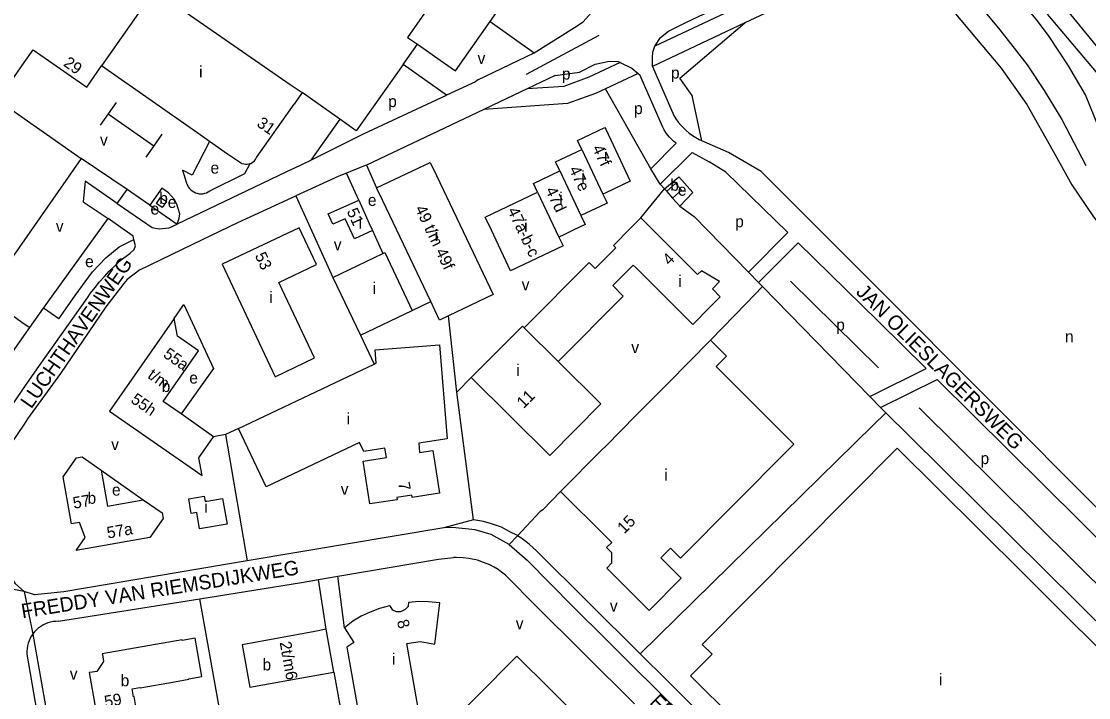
# Model space of a CAD drawing. Extents: x 154765 to 156627, y 383996 to 386132.
# Drawn here: x 155399 to 155766.1, y 385414.8 to 385647.4 of the extents above; entities that cross this region are included whole.
import ezdxf

# ---------------------------------------------------------------- set-up
doc = ezdxf.new("R2010")
doc.units = 0
for name, color, linetype in [('BLT_Basislijn', 7, 'Continuous'), ('BLT_Bebouwing', 7, 'Continuous'), ('BLT_Centroide', 7, 'Continuous'), ('BLT_Huisnummer', 7, 'Continuous'), ('BLT_Huisnummer_reeks', 7, 'Continuous'), ('BLT_Onderverdeling_panden', 7, 'Continuous'), ('BLT_Straatnaam', 7, 'Continuous'), ('BLT_Vlakafsluiter', 7, 'Continuous')]:
    doc.layers.add(name, color=color, linetype=linetype)

msp = doc.modelspace()

# ---------------------------------------------------------------- linework, layer by layer
at = {"layer": 'BLT_Basislijn'}
for p, q in [((155723.16, 385695.09), (155782.92, 385621.52)), ((155560.27, 385647.4), (155575.39, 385636.61)), ((155647.86, 385646.85), (155616.07, 385631.86)), ((155777.49, 385619.55), (155751.97, 385649.86)), ((155530.34, 385632.56), (155535.27, 385639.52)), ((155572.82, 385629.26), (155597.76, 385642.66)), ((155556.04, 385627.27), (155575.39, 385636.61)), ((155616.19, 385636.83), (155616.86, 385638.87)), ((155616.07, 385631.86), (155623.4, 385614.99)), ((155582.65, 385628.77), (155572.99, 385624.19)), ((155611.12, 385629.52), (155599.93, 385624.25)), ((155611.12, 385629.52), (155611.75, 385628.98)), ((155572.99, 385624.19), (155563.61, 385619.74)), ((155615.48, 385596.71), (155599.93, 385624.25)), ((155558.13, 385617.14), (155517.79, 385598.01)), ((155563.61, 385619.74), (155558.13, 385617.14)), ((155633.12, 385606.31), (155632.31, 385606.68)), ((155435.37, 385589.63), (155419.58, 385600.25)), ((155629.7, 385602.29), (155635.61, 385599.15)), ((155492.62, 385596.82), (155452.63, 385577.61)), ((155515.06, 385585.86), (155510.85, 385595.23)), ((155431.98, 385584.75), (155435.37, 385589.63)), ((155441.07, 385585.66), (155435.37, 385589.63)), ((155576.6, 385588.63), (155583.89, 385573.23)), ((155620.29, 385589.76), (155621, 385588.96)), ((155623.04, 385586.63), (155625.52, 385583.84)), ((155625.52, 385583.84), (155630.42, 385580.25)), ((155406.62, 385548.82), (155428.82, 385579.63)), ((155630.42, 385580.25), (155649.08, 385561.15)), ((155519.75, 385575.43), (155523.3, 385567.53)), ((155649.08, 385561.15), (155662.66, 385574.74)), ((155439.8, 385562), (155458.04, 385570.8)), ((155652.57, 385557.58), (155666.24, 385571.25)), ((155649.08, 385561.15), (155652.57, 385557.58)), ((155648.31, 385550.38), (155653.93, 385556.19)), ((155652.57, 385557.58), (155653.93, 385556.19)), ((155653.93, 385556.19), (155690.88, 385518.37)), ((155693.87, 385528.3), (155663.54, 385558.1)), ((155533.49, 385548.01), (155539.85, 385551.04)), ((155401.91, 385542.08), (155406.62, 385548.82)), ((155411.92, 385545.13), (155406.62, 385548.82)), ((155636.09, 385537.77), (155648.31, 385550.38)), ((155548.76, 385519.85), (155545.99, 385546.18)), ((155571.95, 385542.04), (155583.69, 385530.46)), ((155515.62, 385539.49), (155520.38, 385529.51)), ((155690.88, 385518.37), (155710.26, 385527.98)), ((155553.79, 385524.89), (155548.76, 385519.85)), ((155694.55, 385514.61), (155714.02, 385524.27)), ((155554.53, 385476.04), (155548.76, 385519.85)), ((155690.88, 385518.37), (155694.55, 385514.61)), ((155694.55, 385514.61), (155696.37, 385512.8)), ((155813.32, 385409.81), (155707.88, 385514.52)), ((155696.37, 385512.8), (155692.05, 385508.54)), ((155696.37, 385512.8), (155704.4, 385504.85)), ((155473.71, 385507.4), (155469.26, 385505.29)), ((155692.05, 385508.54), (155611.87, 385429.93)), ((155469.26, 385505.29), (155465.15, 385504.52)), ((155469.26, 385505.29), (155476.69, 385461.86)), ((155704.4, 385504.85), (155814.96, 385395.3)), ((155426.46, 385493.05), (155440.95, 385482.9)), ((155554.53, 385476.04), (155544.31, 385473.21)), ((155510.11, 385438.88), (155507.87, 385456.56)), ((155503.88, 385438.34), (155501.23, 385455.42)), ((155411.75, 385441.09), (155460.46, 385448.85)), ((155468.15, 385405.36), (155460.46, 385448.85)), ((155400.95, 385429.81), (155412.57, 385362.07)), ((155608.76, 385426.23), (155608.96, 385426.03)), ((155506.52, 385423.64), (155511.8, 385393.87))]:
    msp.add_line(p, q, dxfattribs=at)
for points in [[(156007.6, 385344.92), (155996.28, 385354.88), (155980.49, 385371.12), (155972.14, 385379.04), (155965.68, 385384.27), (155957.28, 385390.42), (155944.89, 385398.75), (155936.89, 385404.83), (155929.87, 385410.58), (155925.23, 385414.81), (155918.35, 385421.09), (155902.63, 385438.73), (155854.03, 385494.81), (155800.47, 385556.64), (155793.89, 385564.54), (155785.69, 385576.1), (155777.93, 385590.57), (155771.46, 385606.33), (155765, 385622.09), (155759.19, 385632.12), (155752.51, 385642.23), (155748.51, 385647.55), (155714.99, 385688.08)], [(155705.97, 385680.31), (155735.54, 385644.51), (155745.02, 385632.44), (155750.86, 385623.61), (155756.86, 385613.62), (155765.1, 385597.81)], [(155616.86, 385638.87), (155618.82, 385641.82), (155621.63, 385644.09), (155627.62, 385646.96), (155659.11, 385662), (155670.08, 385667.83), (155674.86, 385671.1), (155685.15, 385678.21)], [(155688.15, 385673.62), (155687.58, 385673.11), (155682.11, 385669.63), (155616.86, 385638.87)], [(155699.96, 385674.45), (155691.21, 385668.31), (155685.01, 385664.36), (155647.86, 385646.85)], [(155699.96, 385674.45), (155716.73, 385654.28), (155725.17, 385644.24), (155735.98, 385631.29), (155744.84, 385618.79), (155753.89, 385602.72), (155760.37, 385591.15), (155767.75, 385580.16), (155776.01, 385569.79), (155821.88, 385516.23)], [(155575.39, 385636.61), (155589.29, 385645.25), (155592.25, 385647.23), (155594.99, 385650.37), (155596.39, 385654.14), (155596.54, 385657.23), (155595.72, 385660.82)], [(155633.12, 385606.31), (155629.78, 385621.92), (155625.54, 385627.85), (155647.86, 385646.85)], [(155616.06, 385631.81), (155616.06, 385634.83), (155616.19, 385636.83)], [(155530.34, 385632.56), (155514.2, 385609.78)], [(155545.26, 385622.03), (155530.34, 385632.56)], [(155605.03, 385633.29), (155594.18, 385628.17), (155585.57, 385625.06), (155572.99, 385624.19)], [(155582.65, 385628.77), (155591.04, 385629.97), (155596.44, 385632.74), (155601.35, 385633.77), (155604.34, 385633.63), (155605.03, 385633.29)], [(155605.03, 385633.29), (155609, 385631.33), (155611.12, 385629.52)], [(155615.48, 385596.71), (155624.28, 385605.49), (155623.49, 385606.09), (155622.7, 385606.78), (155621.96, 385607.54), (155621.29, 385608.35), (155620.68, 385609.21), (155620.13, 385610.11), (155619.65, 385611.05), (155619.25, 385612.02), (155611.75, 385628.98)], [(155556.04, 385627.27), (155555.18, 385626.57), (155545.26, 385622.03)], [(155508.57, 385613.75), (155495.57, 385622.9)], [(155498.6, 385599.66), (155516.74, 385608.77), (155545.26, 385622.03)], [(155599.93, 385624.25), (155596.48, 385622.62), (155586.82, 385619.14), (155558.13, 385617.14)], [(155431.63, 385619.54), (155428.88, 385615.63)], [(155428.88, 385615.63), (155426.12, 385611.71)], [(155428.88, 385615.63), (155444.63, 385604.65)], [(155508.57, 385613.75), (155498.6, 385599.66)], [(155514.2, 385609.78), (155508.57, 385613.75)], [(155623.4, 385614.99), (155624.14, 385613.86), (155624.95, 385612.78), (155625.81, 385611.74), (155626.74, 385610.76), (155627.72, 385609.83), (155628.76, 385608.97), (155629.84, 385608.17), (155630.97, 385607.43), (155632.15, 385606.76), (155632.31, 385606.68)], [(155447.38, 385608.56), (155444.63, 385604.65)], [(155463.74, 385606.13), (155457.81, 385594.48), (155454.4, 385596.27)], [(155653.48, 385595.79), (155642.26, 385602.27), (155633.12, 385606.31)], [(155444.63, 385604.65), (155441.88, 385600.73)], [(155492.62, 385596.82), (155498.6, 385599.66)], [(155629.7, 385602.29), (155618.77, 385591.45)], [(155662.66, 385574.74), (155641.38, 385595.56), (155635.61, 385599.15)], [(155454.4, 385596.27), (155455.83, 385591.78), (155455.88, 385591.64), (155456.12, 385591.05), (155456.44, 385590.48), (155456.83, 385589.97), (155457.27, 385589.5), (155457.77, 385589.09), (155458.32, 385588.75), (155458.91, 385588.47), (155459.52, 385588.27), (155460.16, 385588.15), (155460.8, 385588.11), (155461.45, 385588.15), (155462.08, 385588.27), (155462.7, 385588.46), (155463.29, 385588.73), (155463.84, 385589.07), (155475.84, 385595.14), (155477.77, 385598.5)], [(155510.85, 385595.23), (155508.22, 385594.18), (155493.42, 385587.4)], [(155517.79, 385598.01), (155517.28, 385597.8), (155510.85, 385595.23)], [(155517.79, 385598.01), (155521.2, 385590.15)], [(155618.77, 385591.45), (155615.48, 385596.71)], [(155653.48, 385595.79), (155693, 385556.19)], [(155431.98, 385584.75), (155421.02, 385592.43), (155420.27, 385585.32), (155428.82, 385579.63)], [(155620.29, 385589.76), (155618.77, 385591.45)], [(155620.29, 385589.76), (155625.15, 385593.97), (155629.99, 385588.56), (155625.52, 385583.84)], [(155452.63, 385577.61), (155453.35, 385579.71), (155453.56, 385581.25), (155452.98, 385583.05), (155452.45, 385584.58), (155451.66, 385586.17), (155449.59, 385588.44), (155447.37, 385590.08), (155443.19, 385584.18)], [(155612.12, 385579.79), (155620.29, 385589.76)], [(155431.98, 385584.75), (155444.05, 385576.53), (155446.46, 385576.1), (155449.83, 385576.4), (155452.63, 385577.61)], [(155443.19, 385584.18), (155441.07, 385585.66)], [(155443.19, 385584.18), (155452.63, 385577.61)], [(155458.04, 385570.8), (155473.5, 385578.26), (155493.42, 385587.4)], [(155493.42, 385587.4), (155506.19, 385559.36)], [(155437.72, 385572.43), (155437.43, 385573.59), (155431.25, 385577.93), (155428.82, 385579.63)], [(155400, 385521.46), (155405.2, 385529.04), (155421.81, 385552.34), (155422.85, 385553.9), (155424.36, 385555.87), (155425.93, 385557.79), (155427.57, 385559.65), (155429.26, 385561.47), (155431.01, 385563.22), (155432.82, 385564.92), (155433.44, 385565.48), (155436.34, 385567.6), (155437.78, 385568.94), (155438.25, 385570.25), (155437.72, 385572.43)], [(155414.1, 385548.24), (155417.49, 385553.11), (155423.44, 385561.22), (155428.11, 385566.07), (155432.68, 385569.88), (155437.72, 385572.43)], [(155710.26, 385527.98), (155693.74, 385544.35), (155666.24, 385571.25)], [(155439.8, 385562), (155435.38, 385558.64), (155434.27, 385557.21)], [(155583.69, 385530.46), (155606.05, 385552.93), (155602.43, 385556.53), (155609.47, 385563.61), (155610.46, 385562.6), (155629.95, 385543.2), (155635.86, 385549.12)], [(155434.27, 385557.21), (155428.12, 385549.28), (155412.45, 385526.36), (155401.18, 385510.7), (155400, 385508.92)], [(155693, 385556.19), (155770.64, 385478.39)], [(155411.92, 385545.13), (155414.1, 385548.24)], [(155451.62, 385545.26), (155454.92, 385549.99), (155465.11, 385528.06), (155453.94, 385512.39)], [(155571.95, 385542.04), (155571.38, 385542.61), (155553.79, 385524.89)], [(155553.79, 385524.89), (155580.74, 385498.13), (155598.35, 385515.86), (155583.69, 385530.46)], [(155814.96, 385395.3), (155815.81, 385396.15), (155818.5, 385396.69), (155824.21, 385402.45), (155826.6, 385406.47), (155826.75, 385410.3), (155826.12, 385412.36), (155824.68, 385414.68), (155714.02, 385524.27)], [(155383.82, 385490.77), (155384.04, 385492.42), (155384.35, 385494.06), (155384.74, 385495.68), (155385.2, 385497.29), (155385.74, 385498.86), (155386.35, 385500.42), (155387.04, 385501.93), (155387.8, 385503.42), (155389.15, 385505.62), (155400, 385521.46)], [(155400, 385508.92), (155395.45, 385502.1), (155392.4, 385497.33), (155390.49, 385492.93), (155390.21, 385490.83)], [(155400, 385451.33), (155397.05, 385453.93), (155395.65, 385456.27), (155392.92, 385471.02), (155390.15, 385489.01), (155390.21, 385490.83)], [(155584.47, 385485.73), (155578.33, 385479.43), (155577.46, 385478.87), (155569.66, 385470.53)], [(155569.62, 385470.56), (155567, 385471.89), (155564.19, 385473.44), (155560.73, 385474.64), (155557.92, 385475.36), (155554.53, 385476.04)], [(155544.31, 385473.21), (155476.69, 385461.86)], [(155566.78, 385467.46), (155560.62, 385470.91), (155555.14, 385472.54), (155547.33, 385473.33), (155544.31, 385473.21)], [(155569.66, 385470.53), (155566.78, 385467.46)], [(155569.66, 385470.53), (155569.62, 385470.56)], [(155611.87, 385429.93), (155576.24, 385465.34), (155575.07, 385466.41), (155573.68, 385467.61), (155572.19, 385468.81), (155570.82, 385469.75), (155569.66, 385470.53)], [(155566.78, 385467.46), (155572.95, 385462.09), (155588.99, 385445.94), (155600, 385434.96), (155608.76, 385426.23)], [(155507.87, 385456.56), (155542.49, 385462.51), (155547.68, 385462.98)], [(155609.89, 385412.76), (155575.43, 385447), (155566.59, 385455.92), (155565.51, 385457), (155564.19, 385458.03), (155562.99, 385458.85), (155561.59, 385459.71), (155560.11, 385460.47), (155558.02, 385461.34), (155555.91, 385462.06), (155552.98, 385462.73), (155550.98, 385462.93), (155548.56, 385463.03), (155547.68, 385462.98)], [(155476.69, 385461.86), (155413.68, 385451.28), (155403.58, 385450.23), (155400, 385451.33)], [(155501.23, 385455.42), (155507.87, 385456.56)], [(155460.46, 385448.85), (155495.41, 385454.42), (155501.23, 385455.42)], [(155411.75, 385441.09), (155410.83, 385441.07), (155409.92, 385440.97), (155409.02, 385440.79), (155408.13, 385440.54), (155407.27, 385440.21), (155406.45, 385439.8), (155405.66, 385439.33), (155404.92, 385438.79), (155404.22, 385438.18), (155403.58, 385437.52), (155403, 385436.81), (155402.92, 385436.68)], [(155402.92, 385436.68), (155402.49, 385436.05), (155402.04, 385435.24), (155401.67, 385434.4), (155401.36, 385433.53), (155401.14, 385432.64), (155400.99, 385431.73), (155400.93, 385430.81), (155400.95, 385429.81)], [(155402.92, 385436.68), (155416.02, 385362.7)], [(155734.6, 385315.13), (155731.84, 385314.84), (155730.71, 385314.86), (155729.51, 385315.05), (155728.37, 385315.4), (155727.12, 385315.99), (155726.14, 385316.67), (155724.68, 385317.83), (155696.18, 385346.15), (155649.48, 385392.56), (155621.13, 385420.73), (155611.87, 385429.93)], [(155608.96, 385426.03), (155653.28, 385382.33), (155713.58, 385322.08), (155720.5, 385315.89), (155722.31, 385314.59), (155724.99, 385313.76), (155727.79, 385313.46), (155733.17, 385314.1), (155734.6, 385315.13)]]:
    msp.add_lwpolyline(points, dxfattribs=at)
at = {"layer": 'BLT_Bebouwing'}
for p, q in [((155531.87, 385641.88), (155535.27, 385639.52)), ((155460.49, 385608.4), (155426.64, 385632.06)), ((155391.01, 385620.24), (155419.58, 385600.25)), ((155479.95, 385600.6), (155492.81, 385618.95)), ((155463.74, 385606.13), (155460.49, 385608.4)), ((155477.77, 385598.5), (155477.91, 385598.56)), ((155624.06, 385591.68), (155621, 385588.96)), ((155558.54, 385580.07), (155576.6, 385588.63)), ((155621, 385588.96), (155620.99, 385588.95)), ((155620.99, 385588.95), (155623.04, 385586.63)), ((155621.41, 385522.9), (155636.09, 385537.77)), ((155714.34, 385486.7), (155700.3, 385500.65)), ((155728.43, 385472.7), (155714.34, 385486.7)), ((155743.74, 385457.49), (155728.43, 385472.7)), ((155759.92, 385441.42), (155743.74, 385457.49)), ((155780.3, 385421.17), (155759.92, 385441.42)), ((155506.52, 385423.64), (155503.88, 385438.34)), ((155597.88, 385400.95), (155569.49, 385429.14))]:
    msp.add_line(p, q, dxfattribs=at)
for points in [[(155552.89, 385672.11), (155531.87, 385641.88)], [(155560.27, 385647.4), (155574.45, 385667.67)], [(155449.72, 385654.59), (155491.46, 385625.74), (155495.57, 385622.9)], [(155535.27, 385639.52), (155544.27, 385633.26), (155548.38, 385630.4), (155560.27, 385647.4)], [(155400, 385633.24), (155401.14, 385634.88), (155403.04, 385637.61)], [(155403.04, 385637.61), (155421.49, 385624.72), (155426.64, 385632.06)], [(155393.38, 385623.63), (155400, 385633.24)], [(155495.57, 385622.9), (155492.81, 385618.95)], [(155591.77, 385603.34), (155590.31, 385606.42), (155599.72, 385610.88), (155600, 385610.28), (155608.46, 385592.42)], [(155477.77, 385598.5), (155477.23, 385598.33), (155476.67, 385598.23), (155476.11, 385598.22), (155475.55, 385598.28), (155475, 385598.43), (155474.52, 385598.64), (155474.04, 385598.93), (155469.94, 385601.79), (155463.74, 385606.13)], [(155584.18, 385595.99), (155582.73, 385599.06), (155591.77, 385603.34)], [(155419.58, 385600.25), (155386.53, 385553), (155400, 385543.41)], [(155477.91, 385598.56), (155478.28, 385598.74), (155478.75, 385599.06), (155479.17, 385599.44), (155479.53, 385599.87), (155479.83, 385600.35), (155479.95, 385600.6)], [(155521.2, 385590.15), (155539.61, 385598.92), (155541.76, 385594.4), (155561.25, 385553.45), (155545.99, 385546.18)], [(155576.6, 385588.63), (155575.14, 385591.7), (155584.18, 385595.99)], [(155608.46, 385592.42), (155600, 385588.41), (155599.03, 385588.03)], [(155623.04, 385586.63), (155626.12, 385589.36), (155624.06, 385591.68)], [(155539.85, 385551.04), (155523.35, 385585.64), (155521.2, 385590.15)], [(155599.03, 385588.03), (155600, 385585.97), (155600.52, 385584.88), (155600, 385584.64), (155591.48, 385580.6)], [(155506.18, 385577.62), (155504.59, 385581.16), (155515.06, 385585.86)], [(155515.06, 385585.86), (155518.67, 385577.84)], [(155591.48, 385580.6), (155592.94, 385577.52), (155588.78, 385575.55), (155585.57, 385574.02), (155583.89, 385573.23)], [(155519.75, 385575.43), (155513.55, 385572.64), (155510.44, 385579.54), (155506.18, 385577.62)], [(155518.67, 385577.84), (155519.75, 385575.43)], [(155583.89, 385573.23), (155585.35, 385570.16), (155567.29, 385561.6), (155560.68, 385575.55), (155558.54, 385580.07)], [(155571.95, 385542.04), (155594.31, 385564.53), (155596.4, 385562.45), (155603.47, 385569.55), (155602.69, 385570.33), (155608.59, 385576.25), (155612.12, 385579.79)], [(155635.86, 385549.12), (155639.4, 385552.69), (155636.69, 385555.39), (155639.2, 385557.92), (155632.92, 385561.66), (155631.63, 385560.36), (155612.12, 385579.79)], [(155506.19, 385559.36), (155523.3, 385567.53)], [(155523.3, 385567.53), (155524.06, 385567.89), (155533.49, 385548.01)], [(155506.19, 385559.36), (155515.62, 385539.49)], [(155542.88, 385544.7), (155539.85, 385551.04)], [(155515.62, 385539.49), (155533.49, 385548.01)], [(155451.62, 385545.26), (155429.37, 385513.41), (155461.19, 385491.19), (155460.02, 385497.33), (155465.15, 385504.52)], [(155453.94, 385512.39), (155447.77, 385516.72), (155459.94, 385534.1), (155452.7, 385539.12), (155451.62, 385545.26)], [(155545.99, 385546.18), (155542.88, 385544.7)], [(155400, 385543.41), (155401.91, 385542.08)], [(155400, 385539.35), (155401.91, 385542.08)], [(155364.66, 385488.9), (155400, 385539.35)], [(155636.09, 385537.77), (155641.59, 385532.31), (155637.97, 385528.67)], [(155520.38, 385529.51), (155521.08, 385529.84), (155520.72, 385534.43)], [(155520.72, 385534.43), (155542.89, 385536.15), (155545.45, 385503.84)], [(155473.71, 385507.4), (155520.38, 385529.51)], [(155637.97, 385528.67), (155664.75, 385502.05), (155662.72, 385500), (155625.71, 385462.77), (155622.25, 385466.21), (155618.96, 385462.91)], [(155610.51, 385511.94), (155621.41, 385522.9)], [(155465.15, 385504.52), (155453.94, 385512.39)], [(155584.47, 385485.73), (155598.65, 385500), (155600, 385501.36), (155610.51, 385511.94)], [(155516.84, 385499.47), (155515.38, 385502.57), (155483.2, 385487.33), (155473.71, 385507.4)], [(155545.45, 385503.84), (155535.77, 385502.37), (155535.94, 385499.16), (155540.59, 385499.88), (155542.87, 385485.11), (155533.47, 385483.67), (155533.35, 385484.46), (155528.15, 385483.65), (155528.26, 385482.87), (155518.89, 385481.43), (155516.61, 385496.21), (155524.58, 385497.44), (155524.09, 385500.58), (155516.84, 385499.47)], [(155700.3, 385500.65), (155633.2, 385433.14), (155636.59, 385429.78), (155629.15, 385422.38)], [(155417.88, 385465.4), (155421.01, 385469.89), (155419.07, 385475.07), (155416.29, 385474.58), (155413.43, 385490.74), (155418.01, 385497.26), (155419.94, 385497.62), (155426.46, 385493.05)], [(155426.46, 385493.05), (155428.64, 385480.73), (155440.95, 385482.9)], [(155602.09, 385468.22), (155600, 385470.3), (155584.47, 385485.73)], [(155440.95, 385482.9), (155447.46, 385478.34), (155447.84, 385476.44), (155443.24, 385469.88), (155417.88, 385465.4)], [(155456.6, 385483.19), (155461.87, 385484.11), (155462.19, 385482.26), (155468.24, 385483.31), (155469.77, 385474.54), (155460.33, 385472.9), (155459.36, 385478.48), (155457.48, 385478.15), (155456.6, 385483.19)], [(155618.96, 385462.91), (155626.02, 385455.89), (155615.01, 385444.81), (155600.35, 385459.38), (155602.15, 385461.2), (155602.14, 385464.63), (155600.32, 385466.45), (155602.09, 385468.22)], [(155536.01, 385408.59), (155531.6, 385433.44), (155536.17, 385434.12), (155541.26, 385433.17), (155542.97, 385447.47), (155539.09, 385447.76), (155535.73, 385447.91), (155532.18, 385447.51), (155532.08, 385446.13), (155530.99, 385445.13), (155529.44, 385444.32), (155528.08, 385444.39), (155526.84, 385444.92), (155525.96, 385446.13), (155525.7, 385446.41), (155522.21, 385445.52), (155519.04, 385444.2), (155515.87, 385442.87), (155513, 385441.15), (155510.11, 385438.88)], [(155503.88, 385438.34), (155500, 385437.62), (155474.93, 385433.01), (155477.57, 385418.43), (155500, 385422.46), (155506.52, 385423.64)], [(155510.11, 385438.88), (155513.43, 385433.85), (155510.96, 385432.23)], [(155422.54, 385423.48), (155422.32, 385423.45), (155425.29, 385406.62), (155425.49, 385406.64), (155426.29, 385402.17), (155431.21, 385403.03), (155439.48, 385404.47), (155438.67, 385408.98), (155438.86, 385409.02), (155437.78, 385415.19), (155437.56, 385415.16), (155437.1, 385417.87), (155439.79, 385418.33), (155439.86, 385418.16), (155451.73, 385420.27), (155456.65, 385421.14), (155456.61, 385421.36), (155461.12, 385422.1), (155458.81, 385435.33), (155454.33, 385434.53), (155454.31, 385434.73), (155426.84, 385429.85), (155426.87, 385429.64)], [(155510.96, 385432.23), (155515.76, 385405.01), (155536.01, 385408.59)], [(155426.87, 385429.64), (155427.3, 385427.27), (155424.94, 385423.85), (155422.54, 385423.48)], [(155569.49, 385429.14), (155541.46, 385400.93)], [(155629.15, 385422.38), (155690.08, 385361.91), (155697.7, 385369.56), (155693.91, 385373.34)]]:
    msp.add_lwpolyline(points, dxfattribs=at)
for points in [[(155445.46, 385584.75), (155446.89, 385586.81), (155448.9, 385585.42), (155447.46, 385583.36)], [(155494.52, 385576.44), (155468.11, 385563.92), (155486.33, 385525.2), (155499.9, 385531.64), (155487.61, 385557.64), (155500.59, 385563.83)]]:
    msp.add_lwpolyline(points, close=True, dxfattribs=at)
at = {"layer": 'BLT_Onderverdeling_panden'}
for p, q in [((155444.78, 385658.01), (155426.64, 385632.06)), ((155591.77, 385603.34), (155599.03, 385588.03)), ((155584.18, 385595.99), (155591.48, 385580.6))]:
    msp.add_line(p, q, dxfattribs=at)
at = {"layer": 'BLT_Vlakafsluiter'}
for q in [(155389.47, 385453.36), (155402.92, 385436.68)]:
    msp.add_line((155400, 385451.33), q, dxfattribs=at)

# ---------------------------------------------------------------- texts
at = {"layer": 'BLT_Centroide'}
for s, p in [('v', (155555.93, 385632.76)), ('i', (155460.16, 385628.12)), ('p', (155584.94, 385627.38)), ('p', (155622.44, 385627.74)), ('p', (155525.17, 385617.92)), ('p', (155609.76, 385615.51)), ('v', (155426.06, 385604.66)), ('i', (155599.39, 385599.44)), ('e', (155464.08, 385595.05)), ('i', (155591.62, 385591.97)), ('b', (155622.22, 385589.16)), ('b', (155446.44, 385584.59)), ('i', (155584.05, 385584.62)), ('e', (155624.84, 385587.45)), ('e', (155443.42, 385580.97)), ('e', (155449.37, 385583.26)), ('e', (155518.21, 385583.94)), ('i', (155515.01, 385576.14)), ('v', (155410.86, 385575.04)), ('i', (155571.94, 385575.12)), ('p', (155644.54, 385576.61)), ('i', (155541.22, 385571.84)), ('v', (155506.48, 385568.72)), ('e', (155420.94, 385562.88)), ('i', (155625.01, 385556.08)), ('i', (155484.34, 385550.52)), ('i', (155519.84, 385553.69)), ('v', (155571.12, 385554.92)), ('p', (155679.29, 385541.07)), ('n', (155757.98, 385537.04)), ('v', (155608.81, 385533.34)), ('i', (155569.22, 385525.46)), ('e', (155456.78, 385522.85)), ('b', (155447.27, 385519.97)), ('i', (155510.85, 385508.78)), ('v', (155429.91, 385499.96)), ('p', (155728.94, 385495.15)), ('i', (155620.2, 385489.44)), ('b', (155421.78, 385481.5)), ('e', (155430.19, 385484.33)), ('v', (155508.88, 385484.6)), ('i', (155461.92, 385478.5)), ('v', (155601.44, 385444.41)), ('v', (155569.07, 385438.38)), ('i', (155526.53, 385426.12)), ('b', (155481.97, 385424.2)), ('v', (155415.67, 385421.07)), ('b', (155433.17, 385418.75)), ('i', (155714.67, 385419.12))]:
    msp.add_text(s, height=4, dxfattribs=at).set_placement(p)
at = {"layer": 'BLT_Huisnummer'}
for s, rotation, p in [('29', 325.0601, (155413.19, 385632.34)), ('31', 325.3474, (155479.7, 385611.58)), ('47f', 295.3606, (155595.28, 385603.83)), ('47e', 295.3554, (155587.3, 385596.57)), ('47d', 295.3554, (155579.2, 385589.4)), ('51', 294.2173, (155510.85, 385582.14)), ('53', 295.196, (155479.24, 385566.9)), ('4', 45.1135, (155621.96, 385563.24)), ('11', 45.1061, (155571.79, 385514.07)), ('7', 279.7177, (155528.58, 385488.69)), ('15', 45.3299, (155606.4, 385470.95)), ('8', 286.058, (155528.12, 385441.07)), ('59', 9.917, (155427.92, 385411.46))]:
    msp.add_text(s, height=4, rotation=rotation, dxfattribs=at).set_placement(p)
at = {"layer": 'BLT_Huisnummer_reeks'}
for s, rotation, p in [('49 t/m 49f', 295.4579, (155534.33, 385583.04)), ('47a-b-c', 295.3554, (155566.14, 385582.39)), ('55a', 325.0689, (155447.51, 385532.2)), ('t/m', 325.0689, (155442.15, 385525.01)), ('55h', 325.0689, (155436.36, 385516.6)), ('57', 9.8788, (155417.1, 385479.77)), ('57a', 10.0188, (155428.78, 385469.53)), ('2t/m6', 280.2408, (155487.84, 385433.81))]:
    msp.add_text(s, height=4, rotation=rotation, dxfattribs=at).set_placement(p)
at = {"layer": 'BLT_Straatnaam'}
for s, rotation, p in [('LUCHTHAVENWEG', 55.0452, (155402.42, 385513.91)), ('JAN OLIESLAGERSWEG', 315.2803, (155685.81, 385554.03)), ('FREDDY VAN RIEMSDIJKWEG', 9.0549, (155399.39, 385442.06)), ('FREDDY VAN RIEMSDIJKWEG', 315.2104, (155614.87, 385413.01))]:
    msp.add_text(s, height=5, rotation=rotation, dxfattribs=at).set_placement(p)

doc.saveas('drawing.dxf')
